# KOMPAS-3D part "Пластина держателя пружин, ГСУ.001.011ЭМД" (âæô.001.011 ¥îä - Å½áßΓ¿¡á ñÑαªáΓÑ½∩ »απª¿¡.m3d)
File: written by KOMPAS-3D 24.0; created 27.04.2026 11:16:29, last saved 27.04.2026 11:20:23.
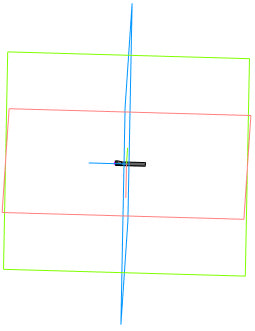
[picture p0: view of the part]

Document properties: Автор: USG_411; Полное имя файла: C:\Users\USG_411\Desktop\ГМ2704_411-15\Двигатель мясорубки\ГСУ.001.011 ЭМД - Пластина держателя пружин.m3d

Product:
- Part/product: Пластина держателя пружин  | designation ГСУ.001.011ЭМД
    Масса: 0.000005

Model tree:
1. Эскиз:1
2. Листовое тело:1
     Расстояние 1 = 10; Толщина листового тела = 0.1; Радиус сгиба = 5
3. Эскиз:2  (with: Грань.Листовое тело:1, Ребро.Листовое тело:1)
4. Сгиб по линии:1  (with: Грань.Листовое тело:1)
     Радиус сгиба = 0.2; Коэффициент = 0.4; Величина сгиба = 10; Радиус сгиба = 0.2; Толщина листового тела = 0.1; Угол сгиба = 199
5. Развертка  (with: Грань.Листовое тело:1)

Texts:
  ГСУ.001.011
  ГСУ.001.011 ЭМД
